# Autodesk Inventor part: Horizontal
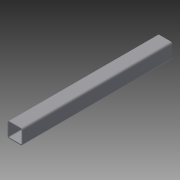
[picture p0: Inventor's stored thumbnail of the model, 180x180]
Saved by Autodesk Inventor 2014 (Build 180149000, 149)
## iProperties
Created: 2008-04
Part Number: Horizontal
Document SubType Name: Modeling
Designer: Jayson Martinez
Density: 1 g/cm^3
Material: Generic
Appearance: Default
Author: Jayson Martinez
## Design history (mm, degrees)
sketch "Sketch1"
  geometry: L1 (6.35, 0)-(44.45, 0); L2 (50.8, 6.35)-(50.8, 44.45); L3 (44.45, 50.8)-(6.35, 50.8); L4 (0, 44.45)-(0, 6.35); L5 (3.175, 6.35)-(3.175, 44.45); L6 (6.35, 47.625)-(44.45, 47.625); L7 (47.625, 44.45)-(47.625, 6.35); L8 (44.45, 3.175)-(6.35, 3.175); A1 r 6.35 centre (44.45, 44.45) between (50.8, 44.45) and (44.45, 50.8); A2 r 6.35 centre (6.35, 44.45) between (6.35, 50.8) and (0, 44.45); A3 r 6.35 centre (6.35, 6.35) between (0, 6.35) and (6.35, 0); A4 r 6.35 centre (44.45, 6.35) between (44.45, 0) and (50.8, 6.35); A5 r 3.175 centre (6.35, 44.45) between (6.35, 47.625) and (3.175, 44.45); A6 r 3.175 centre (44.45, 44.45) between (47.625, 44.45) and (44.45, 47.625); A7 r 3.175 centre (44.45, 6.35) between (44.45, 3.175) and (47.625, 6.35); A8 r 3.175 centre (6.35, 6.35) between (3.175, 6.35) and (6.35, 3.175); 3 further points
  constraints: 16 end point, 16 point on circle, 8 centre point, 8 tangent, 6 point on line, 4 parallel, 3 equal radius, 2 perpendicular, 1 horizontal, 7 other
  dimensions: "d0" = 50.8 distance of point (0, 0) point (50.8, 0) (= MemberWidth); "d1" = 50.8 distance of point (0, 50.8) point (0, 0) (= MemberWidth); "d2" = 6.35 radius of A1 (= 2 x MemberThickness); "d3" = 3.175 distance between parallel lines of L2 L7 (= MemberThickness)
extrude "Extrusion1" new body sketch "Sketch1" distance "d4" = 508 (= HorizontalLength); taper "d5" = 0 deg
body "Solid1"
other parameters: "MemberThickness" = 3.175, "MemberWidth" = 50.8, "HorizontalLength" = 508
